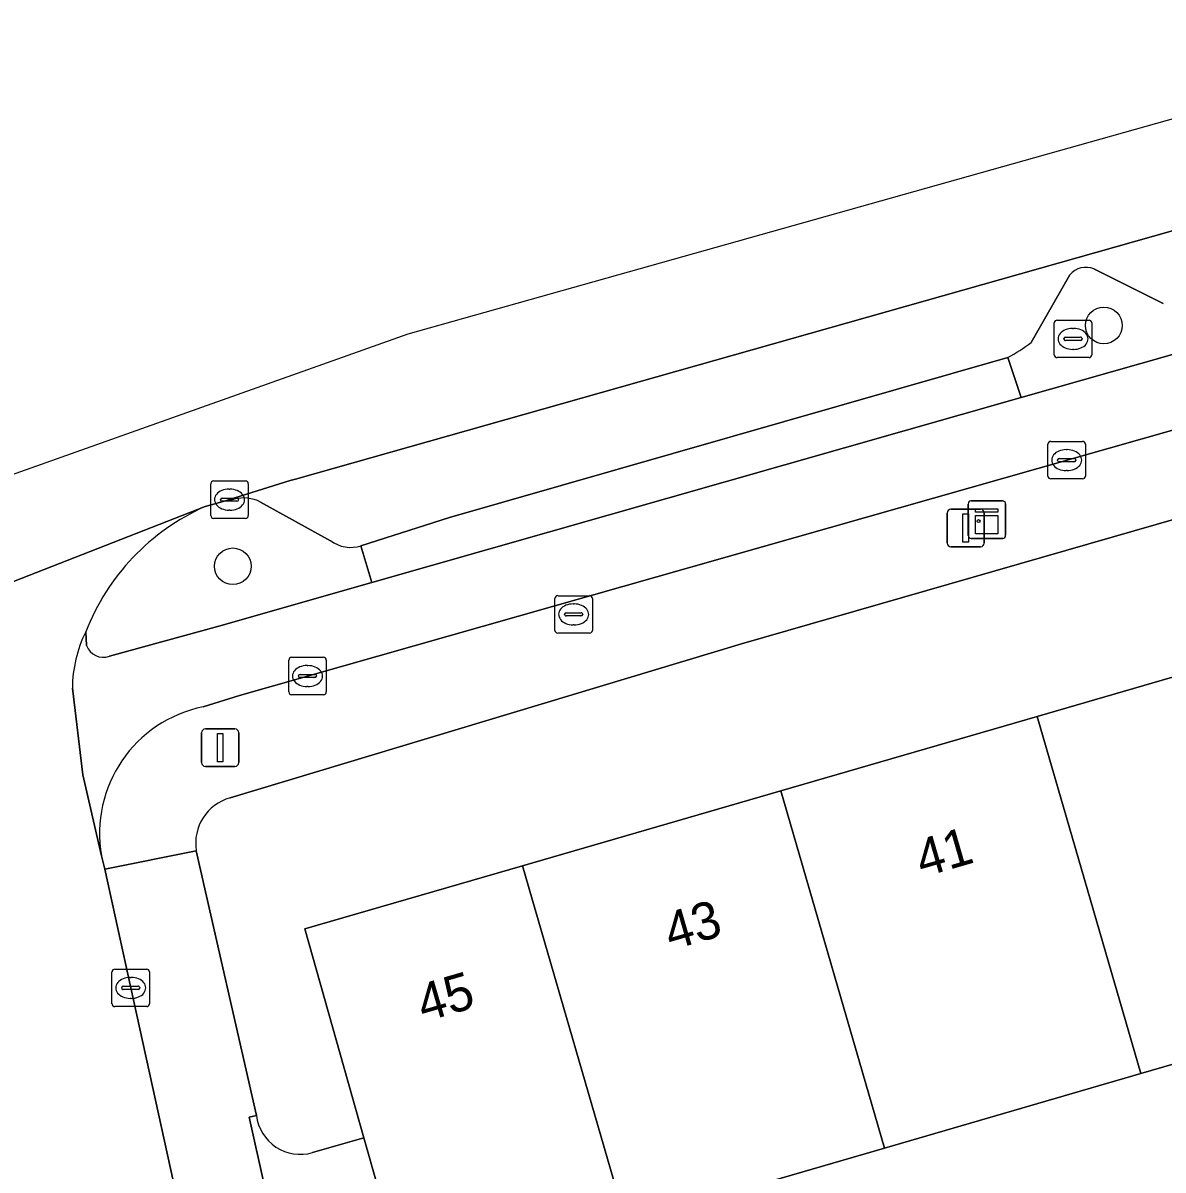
# Model space of a CAD drawing. Extents: x 162073 to 163043, y 381818 to 382561.
# Drawn here: x 162191 to 162221.45, y 382452.09 to 382482.73 of the extents above; entities that cross this region are included whole.
import ezdxf

# ---------------------------------------------------------------- set-up
doc = ezdxf.new("R2010")
doc.units = 0
for name, color, linetype in [('IMGEO_Berm_groen', 7, 'Continuous'), ('IMGEO_Berm_open', 7, 'Continuous'), ('IMGEO_Boom', 7, 'Continuous'), ('IMGEO_Brandkraan', 7, 'Continuous'), ('IMGEO_Erf', 7, 'Continuous'), ('IMGEO_Fietspad_open', 7, 'Continuous'), ('IMGEO_Kast', 7, 'Continuous'), ('IMGEO_Kolk', 7, 'Continuous'), ('IMGEO_Lichtmast', 7, 'Continuous'), ('IMGEO_Pand', 7, 'Continuous'), ('IMGEO_Pand_nummerreeks', 7, 'Continuous'), ('IMGEO_Parkeervlak_open', 7, 'Continuous'), ('IMGEO_Rijbaan_lokaal_gesloten', 7, 'Continuous'), ('IMGEO_Rijbaan_lokaal_open', 7, 'Continuous'), ('IMGEO_Voetpad_open', 7, 'Continuous')]:
    doc.layers.add(name, color=color, linetype=linetype)

msp = doc.modelspace()

# ---------------------------------------------------------------- linework, layer by layer
at = {"layer": 'IMGEO_Berm_groen'}
for points in [[(162221.45, 382475.233), (162219.604, 382476.16)], [(162218.957, 382476.004), (162217.926, 382474.198)], [(162217.304, 382473.794), (162217.656, 382472.724), (162222.483, 382474.099), (162222.174, 382475.171)], [(162196.642, 382470.014), (162196.405, 382469.966), (162195.861, 382469.81)], [(162199.209, 382468.901), (162197.341, 382469.933)], [(162200.318, 382467.785), (162200.026, 382468.762)], [(162193.304, 382465.813), (162196.229, 382466.62), (162200.318, 382467.785)], [(162192.673, 382466.463), (162192.693, 382466.097)]]:
    msp.add_lwpolyline(points, dxfattribs=at)
for centre, radius, start, end in [((162219.384, 382475.651), 0.554, 66.6748, 140.4372), ((162215.11, 382477.853), 4.615, 298.3949, 307.6139), ((162196.879, 382469.005), 1.037, 63.5564, 103.2238), ((162198.337, 382464.26), 6.078, 114.0431, 158.7444), ((162199.756, 382469.644), 0.922, 233.6437, 287.0452), ((162193.146, 382466.272), 0.486, 201.1687, 288.9722)]:
    msp.add_arc(centre, radius, start, end, dxfattribs=at)
at = {"layer": 'IMGEO_Berm_open'}
msp.add_lwpolyline([(162217.656, 382472.724), (162217.304, 382473.794), (162202.389, 382469.522), (162200.026, 382468.762), (162200.318, 382467.785)], close=True, dxfattribs=at)
at = {"layer": 'IMGEO_Boom'}
for centre in [(162219.868, 382474.65), (162196.603, 382468.217)]:
    msp.add_circle(centre, 0.489, dxfattribs=at)
at = {"layer": 'IMGEO_Brandkraan'}
for p, q in [((162205.206, 382466.506), (162205.206, 382467.358)), ((162205.281, 382467.432), (162206.133, 382467.432)), ((162206.207, 382467.358), (162206.207, 382466.506)), ((162205.465, 382466.926), (162205.465, 382466.938)), ((162205.508, 382466.975), (162205.906, 382466.975)), ((162205.694, 382467.212), (162205.719, 382467.212)), ((162205.949, 382466.938), (162205.949, 382466.926)), ((162205.903, 382466.889), (162205.505, 382466.889)), ((162205.717, 382466.652), (162205.692, 382466.652)), ((162206.133, 382466.432), (162205.281, 382466.432))]:
    msp.add_line(p, q, dxfattribs=at)
for points in [[(162205.206, 382466.506), (162205.206, 382467.358)], [(162205.281, 382467.432), (162206.133, 382467.432)], [(162206.207, 382467.358), (162206.207, 382466.506)], [(162206.133, 382466.432), (162205.281, 382466.432)]]:
    msp.add_lwpolyline(points, dxfattribs=at)
for centre, radius, start, end in [((162205.283, 382467.356), 0.0765, 91.552, 178.448), ((162205.283, 382467.356), 0.0765, 91.552, 178.448), ((162206.131, 382467.356), 0.0765, 1.552, 88.448), ((162206.131, 382467.356), 0.0765, 1.552, 88.448), ((162205.505, 382466.935), 0.0403, 85.8775, 175.7526), ((162205.91, 382466.937), 0.0386, 1.7309, 96.639), ((162205.502, 382466.925), 0.0366, 178.938, 274.7102), ((162205.906, 382466.932), 0.043, 264.8664, 352.4533), ((162205.283, 382466.508), 0.0765, 181.552, 268.448), ((162205.283, 382466.508), 0.0765, 181.552, 268.448), ((162206.131, 382466.508), 0.0765, 271.552, 358.448), ((162206.131, 382466.508), 0.0765, 271.552, 358.448)]:
    msp.add_arc(centre, radius, start, end, dxfattribs=at)
for centre, major_axis, ratio, start_param, end_param in [((162205.693, 382466.932), (-0.387, 0.002), 0.722429, 4.712389, 7.853982), ((162205.718, 382466.932), (-0.39, 0.002), 0.717154, 1.570796, 4.712389)]:
    msp.add_ellipse(centre, major_axis=major_axis, ratio=ratio, start_param=start_param, end_param=end_param, dxfattribs=at)
at = {"layer": 'IMGEO_Erf'}
for points in [[(162281.138, 382486.577), (162210.186, 382466.143), (162196.532, 382462.029)], [(162198.731, 382452.553), (162200.106, 382452.948), (162198.53, 382458.53), (162204.342, 382460.216), (162211.24, 382462.219), (162218.089, 382464.206), (162225.039, 382466.224), (162227.194, 382466.849), (162230.087, 382467.689), (162231.71, 382468.16), (162237.782, 382469.922), (162243.726, 382471.647), (162249.76, 382473.398), (162255.807, 382475.153), (162261.214, 382476.722), (162270.049, 382479.286), (162276.217, 382481.076)], [(162195.627, 382460.617), (162197.234, 382453.546)], [(162231.764, 382445.146), (162228.555, 382456.896), (162227.766, 382456.667), (162220.86, 382454.663), (162214.011, 382452.675), (162207.112, 382450.672)]]:
    msp.add_lwpolyline(points, dxfattribs=at)
for centre, radius, start, end in [((162196.862, 382460.822), 1.252, 105.2741, 189.4115), ((162198.404, 382453.685), 1.178, 186.7812, 286.104)]:
    msp.add_arc(centre, radius, start, end, dxfattribs=at)
at = {"layer": 'IMGEO_Fietspad_open'}
for points in [[(162273.231, 382488.5), (162269.839, 382487.545), (162265.001, 382486.183), (162256.653, 382483.833), (162222.483, 382474.099), (162217.656, 382472.724), (162200.318, 382467.785), (162196.229, 382466.62), (162193.304, 382465.813)], [(162195.807, 382464.462), (162196.777, 382464.766), (162257.119, 382481.925)], [(162192.693, 382466.097), (162192.673, 382466.463)], [(162192.318, 382464.96), (162192.593, 382462.648), (162193.098, 382460.48)]]:
    msp.add_lwpolyline(points, dxfattribs=at)
for centre, radius, start, end in [((162195.716, 382464.951), 3.398, 153.5762, 179.845), ((162193.146, 382466.272), 0.486, 201.1687, 288.9722), ((162196.493, 382461.083), 3.448, 101.4804, 190.0638)]:
    msp.add_arc(centre, radius, start, end, dxfattribs=at)
at = {"layer": 'IMGEO_Kast'}
for p, q in [((162216.245, 382469.037), (162216.245, 382469.878)), ((162216.245, 382469.878), (162216.245, 382469.037)), ((162216.32, 382469.962), (162217.161, 382469.962)), ((162217.161, 382469.962), (162216.32, 382469.962)), ((162217.245, 382469.887), (162217.245, 382469.046)), ((162217.245, 382469.046), (162217.245, 382469.887)), ((162217.17, 382468.962), (162216.329, 382468.962)), ((162216.329, 382468.962), (162217.17, 382468.962))]:
    msp.add_line(p, q, dxfattribs=at)
for points in [[(162216.44, 382469.752), (162217.04, 382469.752), (162217.04, 382469.667), (162216.44, 382469.667), (162216.44, 382469.752)], [(162216.44, 382469.577), (162217.04, 382469.577), (162217.04, 382469.088), (162216.44, 382469.088), (162216.44, 382469.577)]]:
    msp.add_lwpolyline(points, dxfattribs=at)
msp.add_circle((162216.524, 382469.426), 0.0377, dxfattribs=at)
for centre, start, end in [((162216.323, 382469.884), 92.4484, 184.2845), ((162216.323, 382469.884), 92.4484, 184.2845), ((162217.167, 382469.884), 2.4484, 94.2845), ((162217.167, 382469.884), 2.4484, 94.2845), ((162216.323, 382469.04), 182.4484, 274.2845), ((162216.323, 382469.04), 182.4484, 274.2845), ((162217.167, 382469.04), 272.4484, 4.2845), ((162217.167, 382469.04), 272.4484, 4.2845)]:
    msp.add_arc(centre, 0.0779, start, end, dxfattribs=at)
at = {"layer": 'IMGEO_Kolk'}
for p, q in [((162218.545, 382473.866), (162218.545, 382474.718)), ((162218.62, 382474.792), (162219.472, 382474.792)), ((162219.546, 382474.718), (162219.546, 382473.866)), ((162218.804, 382474.286), (162218.804, 382474.298)), ((162218.847, 382474.335), (162219.245, 382474.335)), ((162219.033, 382474.572), (162219.058, 382474.572)), ((162219.288, 382474.298), (162219.288, 382474.286)), ((162219.242, 382474.249), (162218.844, 382474.249)), ((162219.056, 382474.012), (162219.031, 382474.012)), ((162219.472, 382473.792), (162218.62, 382473.792)), ((162218.45, 382471.553), (162219.302, 382471.553)), ((162218.375, 382470.627), (162218.375, 382471.479)), ((162218.863, 382471.333), (162218.888, 382471.333)), ((162219.376, 382471.479), (162219.376, 382470.627)), ((162218.634, 382471.047), (162218.634, 382471.059)), ((162219.072, 382471.01), (162218.674, 382471.01)), ((162218.677, 382471.096), (162219.075, 382471.096)), ((162219.118, 382471.059), (162219.118, 382471.047)), ((162218.886, 382470.773), (162218.861, 382470.773)), ((162196.014, 382469.571), (162196.014, 382470.423)), ((162196.089, 382470.497), (162196.941, 382470.497)), ((162197.015, 382470.423), (162197.015, 382469.571)), ((162219.302, 382470.553), (162218.45, 382470.553)), ((162196.273, 382469.991), (162196.273, 382470.003)), ((162196.316, 382470.04), (162196.714, 382470.04)), ((162196.502, 382470.277), (162196.527, 382470.277)), ((162196.757, 382470.003), (162196.757, 382469.991)), ((162196.711, 382469.954), (162196.313, 382469.954)), ((162196.525, 382469.717), (162196.5, 382469.717)), ((162196.941, 382469.497), (162196.089, 382469.497)), ((162198.097, 382464.859), (162198.097, 382465.711)), ((162198.172, 382465.785), (162199.024, 382465.785)), ((162199.098, 382465.711), (162199.098, 382464.859)), ((162198.585, 382465.565), (162198.61, 382465.565)), ((162198.356, 382465.279), (162198.356, 382465.291)), ((162198.794, 382465.242), (162198.396, 382465.242)), ((162198.399, 382465.328), (162198.797, 382465.328)), ((162198.84, 382465.291), (162198.84, 382465.279)), ((162199.024, 382464.785), (162198.172, 382464.785)), ((162198.608, 382465.005), (162198.583, 382465.005)), ((162193.45, 382457.454), (162194.302, 382457.454)), ((162193.375, 382456.528), (162193.375, 382457.38)), ((162193.863, 382457.234), (162193.888, 382457.234)), ((162194.376, 382457.38), (162194.376, 382456.528)), ((162193.634, 382456.948), (162193.634, 382456.96)), ((162194.072, 382456.911), (162193.674, 382456.911)), ((162193.677, 382456.997), (162194.075, 382456.997)), ((162194.118, 382456.96), (162194.118, 382456.948)), ((162193.886, 382456.674), (162193.861, 382456.674)), ((162194.302, 382456.454), (162193.45, 382456.454))]:
    msp.add_line(p, q, dxfattribs=at)
for points in [[(162218.545, 382473.866), (162218.545, 382474.718)], [(162218.62, 382474.792), (162219.472, 382474.792)], [(162219.546, 382474.718), (162219.546, 382473.866)], [(162219.472, 382473.792), (162218.62, 382473.792)], [(162218.45, 382471.553), (162219.302, 382471.553)], [(162218.375, 382470.627), (162218.375, 382471.479)], [(162219.376, 382471.479), (162219.376, 382470.627)], [(162196.014, 382469.571), (162196.014, 382470.423)], [(162196.089, 382470.497), (162196.941, 382470.497)], [(162197.015, 382470.423), (162197.015, 382469.571)], [(162219.302, 382470.553), (162218.45, 382470.553)], [(162196.941, 382469.497), (162196.089, 382469.497)], [(162198.097, 382464.859), (162198.097, 382465.711)], [(162198.172, 382465.785), (162199.024, 382465.785)], [(162199.098, 382465.711), (162199.098, 382464.859)], [(162199.024, 382464.785), (162198.172, 382464.785)], [(162193.45, 382457.454), (162194.302, 382457.454)], [(162193.375, 382456.528), (162193.375, 382457.38)], [(162194.376, 382457.38), (162194.376, 382456.528)], [(162194.302, 382456.454), (162193.45, 382456.454)]]:
    msp.add_lwpolyline(points, dxfattribs=at)
for centre, radius, start, end in [((162218.622, 382474.716), 0.0765, 91.552, 178.448), ((162218.622, 382474.716), 0.0765, 91.552, 178.448), ((162219.47, 382474.716), 0.0765, 1.552, 88.448), ((162219.47, 382474.716), 0.0765, 1.552, 88.448), ((162218.844, 382474.295), 0.0403, 85.8775, 175.7526), ((162218.841, 382474.285), 0.0366, 178.938, 274.7102), ((162219.245, 382474.292), 0.043, 264.8664, 352.4533), ((162219.249, 382474.297), 0.0386, 1.7309, 96.639), ((162218.622, 382473.868), 0.0765, 181.552, 268.448), ((162218.622, 382473.868), 0.0765, 181.552, 268.448), ((162219.47, 382473.868), 0.0765, 271.552, 358.448), ((162219.47, 382473.868), 0.0765, 271.552, 358.448), ((162218.452, 382471.477), 0.0765, 91.552, 178.448), ((162218.452, 382471.477), 0.0765, 91.552, 178.448), ((162219.3, 382471.477), 0.0765, 1.552, 88.448), ((162219.3, 382471.477), 0.0765, 1.552, 88.448), ((162218.674, 382471.056), 0.0403, 85.8775, 175.7526), ((162218.671, 382471.046), 0.0366, 178.938, 274.7102), ((162219.075, 382471.053), 0.043, 264.8664, 352.4533), ((162219.079, 382471.058), 0.0386, 1.7309, 96.639), ((162218.452, 382470.629), 0.0765, 181.552, 268.448), ((162218.452, 382470.629), 0.0765, 181.552, 268.448), ((162219.3, 382470.629), 0.0765, 271.552, 358.448), ((162219.3, 382470.629), 0.0765, 271.552, 358.448), ((162196.091, 382470.421), 0.0765, 91.552, 178.448), ((162196.091, 382470.421), 0.0765, 91.552, 178.448), ((162196.939, 382470.421), 0.0765, 1.552, 88.448), ((162196.939, 382470.421), 0.0765, 1.552, 88.448), ((162196.313, 382470), 0.0403, 85.8775, 175.7526), ((162196.718, 382470.002), 0.0386, 1.7309, 96.639), ((162196.31, 382469.99), 0.0366, 178.938, 274.7102), ((162196.714, 382469.997), 0.043, 264.8664, 352.4533), ((162196.091, 382469.573), 0.0765, 181.552, 268.448), ((162196.091, 382469.573), 0.0765, 181.552, 268.448), ((162196.939, 382469.573), 0.0765, 271.552, 358.448), ((162196.939, 382469.573), 0.0765, 271.552, 358.448), ((162198.174, 382465.709), 0.0765, 91.552, 178.448), ((162198.174, 382465.709), 0.0765, 91.552, 178.448), ((162199.022, 382465.709), 0.0765, 1.552, 88.448), ((162199.022, 382465.709), 0.0765, 1.552, 88.448), ((162198.396, 382465.288), 0.0403, 85.8775, 175.7526), ((162198.393, 382465.278), 0.0366, 178.938, 274.7102), ((162198.797, 382465.285), 0.043, 264.8664, 352.4533), ((162198.801, 382465.29), 0.0386, 1.7309, 96.639), ((162198.174, 382464.861), 0.0765, 181.552, 268.448), ((162198.174, 382464.861), 0.0765, 181.552, 268.448), ((162199.022, 382464.861), 0.0765, 271.552, 358.448), ((162199.022, 382464.861), 0.0765, 271.552, 358.448), ((162193.452, 382457.378), 0.0765, 91.552, 178.448), ((162193.452, 382457.378), 0.0765, 91.552, 178.448), ((162194.3, 382457.378), 0.0765, 1.552, 88.448), ((162194.3, 382457.378), 0.0765, 1.552, 88.448), ((162193.674, 382456.957), 0.0403, 85.8775, 175.7526), ((162193.671, 382456.947), 0.0366, 178.938, 274.7102), ((162194.075, 382456.954), 0.043, 264.8664, 352.4533), ((162194.079, 382456.959), 0.0386, 1.7309, 96.639), ((162193.452, 382456.53), 0.0765, 181.552, 268.448), ((162193.452, 382456.53), 0.0765, 181.552, 268.448), ((162194.3, 382456.53), 0.0765, 271.552, 358.448), ((162194.3, 382456.53), 0.0765, 271.552, 358.448)]:
    msp.add_arc(centre, radius, start, end, dxfattribs=at)
for centre, major_axis, ratio, start_param, end_param in [((162219.032, 382474.292), (-0.387, 0.002), 0.722429, 4.712389, 7.853982), ((162219.057, 382474.292), (-0.39, 0.002), 0.717154, 1.570796, 4.712389), ((162218.862, 382471.053), (-0.387, 0.002), 0.722429, 4.712389, 7.853982), ((162218.887, 382471.053), (-0.39, 0.002), 0.717154, 1.570796, 4.712389), ((162196.501, 382469.997), (-0.387, 0.002), 0.722429, 4.712389, 7.853982), ((162196.526, 382469.997), (-0.39, 0.002), 0.717154, 1.570796, 4.712389), ((162198.584, 382465.285), (-0.387, 0.002), 0.722429, 4.712389, 7.853982), ((162198.609, 382465.285), (-0.39, 0.002), 0.717154, 1.570796, 4.712389), ((162193.862, 382456.954), (-0.387, 0.002), 0.722429, 4.712389, 7.853982), ((162193.887, 382456.954), (-0.39, 0.002), 0.717154, 1.570796, 4.712389)]:
    msp.add_ellipse(centre, major_axis=major_axis, ratio=ratio, start_param=start_param, end_param=end_param, dxfattribs=at)
at = {"layer": 'IMGEO_Lichtmast'}
for p, q in [((162215.785, 382469.739), (162216.575, 382469.739)), ((162216.575, 382469.739), (162215.785, 382469.739)), ((162215.685, 382468.839), (162215.685, 382469.639)), ((162215.685, 382469.639), (162215.685, 382468.839)), ((162216.675, 382469.639), (162216.675, 382468.839)), ((162216.675, 382468.839), (162216.675, 382469.639)), ((162216.575, 382468.739), (162215.785, 382468.739)), ((162215.785, 382468.739), (162216.575, 382468.739)), ((162195.869, 382463.871), (162196.659, 382463.871)), ((162196.659, 382463.871), (162195.869, 382463.871)), ((162195.769, 382462.971), (162195.769, 382463.771)), ((162195.769, 382463.771), (162195.769, 382462.971)), ((162196.759, 382463.771), (162196.759, 382462.971)), ((162196.759, 382462.971), (162196.759, 382463.771)), ((162196.659, 382462.871), (162195.869, 382462.871)), ((162195.869, 382462.871), (162196.659, 382462.871))]:
    msp.add_line(p, q, dxfattribs=at)
for points in [[(162216.105, 382469.614), (162216.255, 382469.614), (162216.255, 382468.864), (162216.105, 382468.864), (162216.105, 382469.614)], [(162196.189, 382463.746), (162196.339, 382463.746), (162196.339, 382462.996), (162196.189, 382462.996), (162196.189, 382463.746)]]:
    msp.add_lwpolyline(points, dxfattribs=at)
for centre, start, end in [((162215.785, 382469.639), 90, 180), ((162215.785, 382469.639), 90, 180), ((162216.575, 382469.639), 0, 90), ((162216.575, 382469.639), 360, 90), ((162215.785, 382468.839), 180, 270), ((162215.785, 382468.839), 180, 270), ((162216.575, 382468.839), 270, 0), ((162216.575, 382468.839), 270, 0), ((162195.869, 382463.771), 90, 180), ((162195.869, 382463.771), 90, 180), ((162196.659, 382463.771), 0, 90), ((162196.659, 382463.771), 360, 90), ((162195.869, 382462.971), 180, 270), ((162195.869, 382462.971), 180, 270), ((162196.659, 382462.971), 270, 0), ((162196.659, 382462.971), 270, 0)]:
    msp.add_arc(centre, 0.1, start, end, dxfattribs=at)
at = {"layer": 'IMGEO_Pand'}
for points in [[(162227.766, 382456.667), (162225.039, 382466.224), (162218.089, 382464.206), (162220.86, 382454.663)], [(162211.24, 382462.219), (162214.011, 382452.675), (162220.86, 382454.663), (162218.089, 382464.206)], [(162211.24, 382462.219), (162204.342, 382460.216), (162207.112, 382450.672), (162214.011, 382452.675)], [(162207.112, 382450.672), (162204.342, 382460.216), (162198.53, 382458.53), (162200.106, 382452.948), (162200.468, 382451.668), (162200.597, 382451.214), (162198.756, 382450.695), (162199.641, 382447.572), (162199.981, 382446.369), (162203.687, 382447.419), (162204.371, 382448.642), (162204.048, 382449.783)]]:
    msp.add_lwpolyline(points, close=True, dxfattribs=at)
at = {"layer": 'IMGEO_Parkeervlak_open'}
for points in [[(162272.662, 382491.623), (162198.275, 382470.548), (162198.13, 382470.507), (162196.514, 382469.997), (162196.405, 382469.966), (162196.642, 382470.014)], [(162219.604, 382476.16), (162221.45, 382475.233)], [(162217.926, 382474.198), (162218.957, 382476.004)], [(162200.026, 382468.762), (162202.389, 382469.522), (162217.304, 382473.794)], [(162197.341, 382469.933), (162199.209, 382468.901)]]:
    msp.add_lwpolyline(points, dxfattribs=at)
for centre, radius, start, end in [((162219.384, 382475.651), 0.554, 66.6748, 140.4372), ((162215.11, 382477.853), 4.615, 298.3949, 307.6139), ((162196.879, 382469.005), 1.037, 63.5564, 103.2238), ((162199.756, 382469.644), 0.922, 233.6437, 287.0452)]:
    msp.add_arc(centre, radius, start, end, dxfattribs=at)
at = {"layer": 'IMGEO_Rijbaan_lokaal_gesloten'}
for points in [[(162315.724, 382511.35), (162306.448, 382506.279), (162282.905, 382497.501), (162245.387, 382486.842), (162201.279, 382474.422), (162185.966, 382468.979), (162180.588, 382467.067), (162160.813, 382456.745), (162145.022, 382444.832), (162130.306, 382431.424), (162118.152, 382417.002), (162108.457, 382405.716), (162072.514, 382380.58)], [(162176.456, 382462.089), (162177.565, 382462.654), (162179.019, 382463.222), (162195.861, 382469.81), (162196.405, 382469.966), (162196.514, 382469.997), (162198.13, 382470.507), (162198.275, 382470.548), (162272.662, 382491.623)]]:
    msp.add_lwpolyline(points, dxfattribs=at)
at = {"layer": 'IMGEO_Rijbaan_lokaal_open'}
for points in [[(162195.861, 382469.81), (162179.019, 382463.222)], [(162187.981, 382455.501), (162188.481, 382453.776), (162189.469, 382449.352), (162189.611, 382448.718), (162190.524, 382444.432), (162190.555, 382444.279), (162195.379, 382422.687), (162199.089, 382406.015), (162205.027, 382407.332), (162202.838, 382417.222), (162198.3, 382437.064), (162197.549, 382440.349), (162195.44, 382449.86), (162193.875, 382456.953), (162193.181, 382460.122), (162193.098, 382460.48), (162192.593, 382462.648), (162192.318, 382464.96)]]:
    msp.add_lwpolyline(points, dxfattribs=at)
for centre, radius, start, end in [((162198.337, 382464.26), 6.078, 114.0431, 158.7444), ((162195.716, 382464.951), 3.398, 153.5762, 179.845)]:
    msp.add_arc(centre, radius, start, end, dxfattribs=at)
at = {"layer": 'IMGEO_Voetpad_open'}
for points in [[(162273.742, 382486.587), (162257.119, 382481.925), (162196.777, 382464.766), (162195.807, 382464.462)], [(162196.532, 382462.029), (162210.186, 382466.143), (162281.138, 382486.577)], [(162193.098, 382460.48), (162193.181, 382460.122), (162195.627, 382460.617)], [(162212.159, 382387.115), (162201.749, 382433.363), (162201.058, 382436.718), (162200.87, 382437.541), (162198.644, 382447.29), (162198.054, 382449.871), (162197.859, 382449.827), (162197.039, 382453.502), (162197.234, 382453.546), (162195.627, 382460.617), (162193.181, 382460.122), (162193.875, 382456.953), (162195.44, 382449.86), (162197.549, 382440.349), (162198.035, 382440.464), (162198.788, 382437.179), (162198.3, 382437.064), (162202.838, 382417.222)], [(162197.234, 382453.546), (162197.039, 382453.502), (162197.859, 382449.827), (162198.054, 382449.871)], [(162199.057, 382451.205), (162200.468, 382451.668), (162200.106, 382452.948), (162198.731, 382452.553)]]:
    msp.add_lwpolyline(points, dxfattribs=at)
for centre, radius, start, end in [((162196.493, 382461.083), 3.448, 101.4804, 190.0638), ((162196.862, 382460.822), 1.252, 105.2741, 189.4115), ((162198.404, 382453.685), 1.178, 186.7812, 286.104)]:
    msp.add_arc(centre, radius, start, end, dxfattribs=at)

# ---------------------------------------------------------------- texts
at = {"layer": 'IMGEO_Pand_nummerreeks'}
for s, p in [('41', (162215.016, 382459.899)), ('43', (162208.302, 382457.951)), ('45', (162201.697, 382456.034))]:
    msp.add_text(s, height=1, rotation=16.1848, dxfattribs=at).set_placement(p)

doc.saveas('drawing.dxf')
